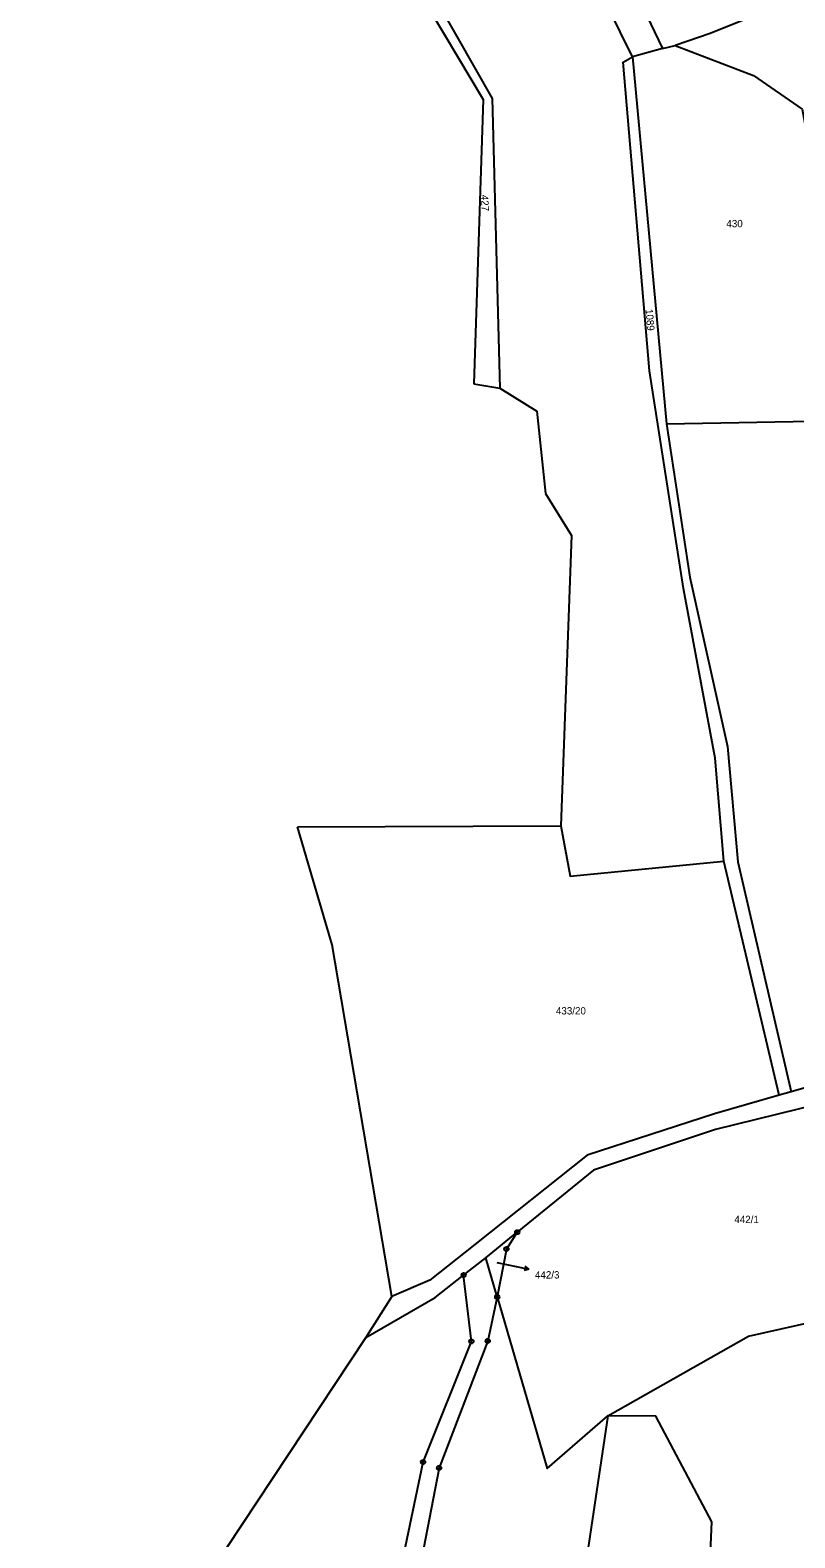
# Model space of a CAD drawing. Extents: x -680203 to -673936, y -1102717 to -1093650.
# Drawn here: x -680025.3 to -679847.8, y -1098550.5 to -1098200.7 of the extents above; entities that cross this region are included whole.
import ezdxf

# ---------------------------------------------------------------- set-up
doc = ezdxf.new("R2010")
doc.units = 0
for name, color, linetype in [('SOxx02xx_Koleje_param další_Popis10', 7, 'Continuous'), ('SOxx02xx_Staničení_Popis10', 7, 'Continuous'), ('SOxxxxxx_Osa_bod_P', 7, 'Continuous'), ('x_prac', 7, 'Continuous')]:
    doc.layers.add(name, color=color, linetype=linetype)

msp = doc.modelspace()

# ---------------------------------------------------------------- linework, layer by layer
at = {"layer": 'SOxx02xx_Koleje_param další_Popis10'}
for centre, radius in [((-679912.25, -1098479.59), 0.5), ((-679912.25, -1098479.59), 0.0303), ((-679914.76, -1098483.52), 0.5), ((-679914.76, -1098483.52), 0.0303), ((-679924.69, -1098489.56), 0.5), ((-679924.69, -1098489.56), 0.0303), ((-679916.91, -1098494.61), 0.5), ((-679916.91, -1098494.61), 0.0303), ((-679922.89, -1098504.95), 0.5), ((-679922.89, -1098504.95), 0.0303), ((-679919.1, -1098504.83), 0.5), ((-679919.1, -1098504.83), 0.0303), ((-679934.11, -1098532.93), 0.5), ((-679934.11, -1098532.93), 0.0303), ((-679930.39, -1098534.28), 0.5), ((-679930.39, -1098534.28), 0.0303)]:
    msp.add_circle(centre, radius, dxfattribs=at)
at = {"layer": 'SOxx02xx_Staničení_Popis10'}
for p, q in [((-679917, -1098486.64), (-679912.5, -1098487.57)), ((-679912.5, -1098487.57), (-679909.57, -1098488.19)), ((-679909.57, -1098488.19), (-679910.65, -1098488.48)), ((-679909.57, -1098488.19), (-679910.44, -1098487.5))]:
    msp.add_line(p, q, dxfattribs=at)
at = {"layer": 'x_prac'}
for p, q in [((-679878.56, -1098204.95), (-679885.5, -1098206.93)), ((-679878.56, -1098204.95), (-679875.6, -1098204.31)), ((-679885.5, -1098206.93), (-679877.61, -1098292.02)), ((-679922.35, -1098282.77), (-679916.32, -1098283.78)), ((-679916.32, -1098283.78), (-679907.7, -1098289.14)), ((-679907.7, -1098289.14), (-679905.7, -1098308.18)), ((-679877.61, -1098292.02), (-679838.77, -1098291.34)), ((-679905.7, -1098308.18), (-679899.64, -1098317.94)), ((-679899.64, -1098317.94), (-679902.11, -1098385.34)), ((-679963.25, -1098385.54), (-679902.11, -1098385.34)), ((-679851.49, -1098447.82), (-679864.32, -1098393.51)), ((-679817.82, -1098438.12), (-679848.73, -1098447.02)), ((-679848.73, -1098447.02), (-679851.49, -1098447.82)), ((-679851.49, -1098447.82), (-679866.46, -1098452.13)), ((-679919.56, -1098485.53), (-679912.25, -1098479.59)), ((-679924.69, -1098489.56), (-679919.56, -1098485.53)), ((-679916.91, -1098494.61), (-679919.56, -1098485.53)), ((-679941.35, -1098494.53), (-679947.35, -1098504.03)), ((-679947.35, -1098504.03), (-680010.62, -1098599.5)), ((-679891.26, -1098522.22), (-679898.99, -1098573.98))]:
    msp.add_line(p, q, dxfattribs=at)
for points in [[(-680025.27, -1097911.61), (-680005.28, -1097950.81), (-679941.2, -1098077.06), (-679902.29, -1098155.38), (-679878.56, -1098204.95)], [(-679885.5, -1098206.93), (-679911.39, -1098154.28), (-679969.42, -1098045.11), (-680008.66, -1097966.29), (-680018.89, -1097946.34)], [(-679965.16, -1098141.3), (-679962.53, -1098138.49), (-679918.07, -1098216.55), (-679916.32, -1098283.78)], [(-679965.16, -1098141.3), (-679920.17, -1098216.79), (-679922.35, -1098282.77)], [(-679856.1, -1098196.93), (-679867.52, -1098201.52), (-679875.6, -1098204.31)], [(-679875.6, -1098204.31), (-679857.43, -1098211.27), (-679846.12, -1098219.03), (-679844.37, -1098228.6)], [(-679864.32, -1098393.51), (-679866.31, -1098369.65), (-679873.72, -1098330.24), (-679881.56, -1098279.77), (-679887.69, -1098208.12), (-679885.5, -1098206.93)], [(-679877.61, -1098292.02), (-679872.22, -1098327.6), (-679863.51, -1098366.89), (-679861.11, -1098393.69), (-679848.73, -1098447.02)], [(-679941.35, -1098494.53), (-679955.18, -1098412.94), (-679963.25, -1098385.54)], [(-679902.11, -1098385.34), (-679899.94, -1098396.99), (-679864.32, -1098393.51)], [(-679818.48, -1098444.04), (-679866.23, -1098455.74), (-679894.54, -1098465.2), (-679912.25, -1098479.59)], [(-679866.46, -1098452.13), (-679896.06, -1098461.75), (-679922.11, -1098482.49), (-679932.57, -1098490.71), (-679941.35, -1098494.53)], [(-679912.25, -1098479.59), (-679914.76, -1098483.52), (-679916.91, -1098494.61)], [(-679953.05, -1098630.1), (-679941.06, -1098610.99), (-679937.61, -1098602.19), (-679937.43, -1098594.09), (-679940.61, -1098573.55), (-679939.16, -1098557.28), (-679934.11, -1098532.93), (-679922.89, -1098504.95), (-679924.69, -1098489.56)], [(-679947.35, -1098504.03), (-679931.27, -1098494.73), (-679924.69, -1098489.56)], [(-679916.91, -1098494.61), (-679919.1, -1098504.83), (-679930.39, -1098534.28), (-679934.93, -1098557.85), (-679936.52, -1098573.06), (-679933.13, -1098593.3), (-679931.29, -1098602.71)], [(-679916.91, -1098494.61), (-679905.29, -1098534.43), (-679891.26, -1098522.22)], [(-679891.26, -1098522.22), (-679858.61, -1098503.69), (-679813.15, -1098493.53)], [(-679812.14, -1098557.5), (-679860.22, -1098578.95), (-679867.54, -1098557.49), (-679867.14, -1098546.77), (-679880.1, -1098522.31), (-679891.26, -1098522.22)]]:
    msp.add_lwpolyline(points, dxfattribs=at)

# ---------------------------------------------------------------- texts
at = {"layer": 'SOxxxxxx_Osa_bod_P'}
for s, rotation, p in [('427', 272, (-679920.66, -1098238.95)), ('1089', 275, (-679882.5, -1098265.49))]:
    msp.add_text(s, height=1.7, rotation=rotation, dxfattribs=at).set_placement(p)
for s, p in [('430', (-679863.73, -1098246.44)), ('433/20', (-679903.28, -1098429.08)), ('442/1', (-679861.89, -1098477.49)), ('442/3', (-679908.15, -1098490.34))]:
    msp.add_text(s, height=1.7, dxfattribs=at).set_placement(p)

doc.saveas('drawing.dxf')
